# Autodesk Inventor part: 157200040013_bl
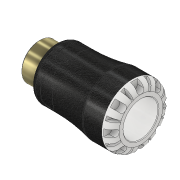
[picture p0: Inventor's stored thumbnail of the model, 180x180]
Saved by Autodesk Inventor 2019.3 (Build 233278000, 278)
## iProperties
Created: 2016-12
Part Number: 157200040013_bl
Material: PVC-Piping
Description: PLASSON  G-PLASS BRASS MALE ADAPTOR 40X 1 1/4" SERIES 1
Document SubType Name: Modeling
Designer: KIM
Mass: 61.7504 g
Surface Area: 140.097 cm^2
Volume: 44.1074 cm^3
Density: 1.4 g/cm^3
Appearance: Black Cast
Author: KIM
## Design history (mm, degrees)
derived "157200.ipt"
feature "Solid1::157200.ipt" dims "ScaleForDerivedMember" = 10
tag "TaggingFeature1"
body "Solid1"
other parameters: "d0" = 117 [user parameter], "d1" = 31.92 [user parameter], "d6" = 76 [user parameter], "d8" = 59.5 [user parameter], "d13" = 8 [user parameter], "d14" = 8 [user parameter], "d15" = 0 [user parameter], "d17" = 360 deg [user parameter], "d19" = 8 deg [user parameter], "d20" = 0.8 [user parameter], "d21" = 0.8 [user parameter], "d22" = 8 deg [user parameter], "d24" = 0 [user parameter], "d26" = 360 deg [user parameter], "d32" = 7 [user parameter], "d33" = 7 [user parameter], "d34" = 41.91 [user parameter], "d38" = 19 [user parameter], "d39" = 1.2573 [user parameter], "d42" = 14 [user parameter], "d43" = 9.2 [user parameter], "d45" = 15.68 [user parameter], "d46" = 0 [user parameter], "d59" = 360 deg [user parameter], "d61" = 11.9 [user parameter], "d62" = 0.8 [user parameter], "d64" = 0 [user parameter], "d65" = 0.7 [user parameter], "d68" = 5.71429 [user parameter], "H_" = 117 [user parameter], "l_" = 76 [user parameter], "R_" = 41.91 [user parameter], "l_2" = 19 [user parameter], "d9" = 10 [user parameter]
